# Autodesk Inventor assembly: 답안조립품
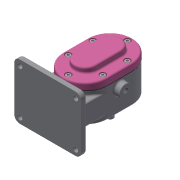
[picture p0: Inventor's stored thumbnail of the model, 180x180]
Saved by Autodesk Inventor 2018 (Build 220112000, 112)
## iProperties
Created: 2020-09
Part Number: 답안조립품
Document SubType Name: Assembly
Designer: Administrator
Author: Administrator
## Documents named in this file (11)
- C:\Users\Administrator\Desktop\700906V1051\답안조립품.iam
- C:\Users\Administrator\Desktop\700906V1051\본체.ipt
- C:\Users\Administrator\Desktop\700906V1051\볼트 M5.ipt
- C:\Users\Administrator\Desktop\700906V1051\메인축.ipt
- C:\Users\Administrator\Desktop\700906V1051\베어링부시.ipt
- C:\Users\Administrator\Desktop\700906V1051\스퍼기어.ipt
- C:\Users\Administrator\Desktop\700906V1051\키 6 x 6 x 18.ipt
- C:\Users\Administrator\Desktop\700906V1051\개스킷.ipt
- C:\Users\Administrator\Desktop\700906V1051\서브축.ipt
- C:\Users\Administrator\Desktop\700906V1051\오일 실 16 28 7.ipt
- C:\Users\Administrator\Desktop\700906V1051\커버.ipt
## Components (1 placed, 1 different names)
1. 개스킷:1
